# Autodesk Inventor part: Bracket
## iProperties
Shininess: 77.0
Length Units: 11269
Angle Units: 11279
Time Units: 11290
Mass Units: 11283
Length Display Precision: 3
Angle Display Precision: 2
Created: 2002-04
Part Number: Bracket
Document SubType Name: Modeling
Density: 0.0
Volumn: 0.0
Area: 0.0
PropertySet Name: Model Information
Control State: 0
Master: False
Checked Out: False
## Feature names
1. Extrusion1
2. Shell1
